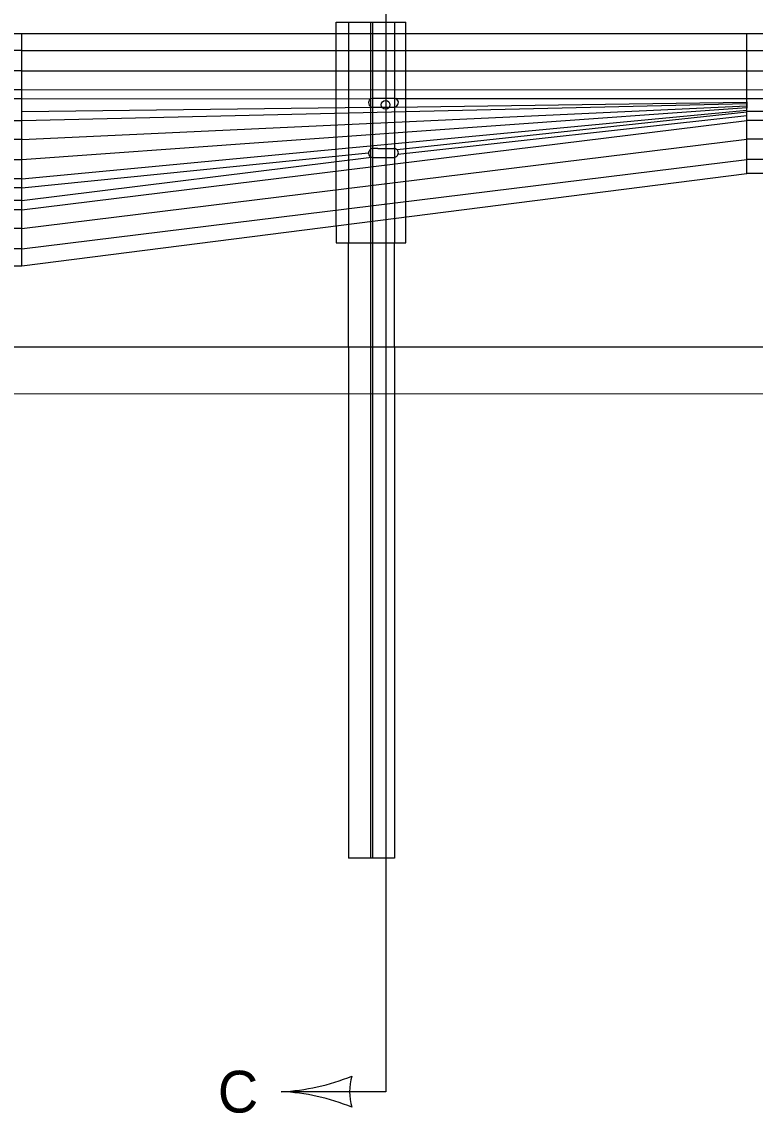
# Model space of a CAD drawing. Extents: x 49991 to 50160, y 49948 to 50051.
# Drawn here: x 50004.55 to 50005.602, y 49993.953 to 49995.519 of the extents above; entities that cross this region are included whole.
import ezdxf

# ---------------------------------------------------------------- set-up
doc = ezdxf.new("R2010")
doc.units = 0
for name, color, linetype in [('Level 1', 7, 'Continuous'), ('Level 2', 7, 'Continuous'), ('Level 3', 7, 'Continuous'), ('Level 4', 7, 'Continuous'), ('Level 6', 7, 'Continuous')]:
    doc.layers.add(name, color=color, linetype=linetype)

msp = doc.modelspace()

# ---------------------------------------------------------------- linework, layer by layer
at = {"layer": 'Level 1'}
for p, q in [((50005.0008, 49995.5185), (50005.1008, 49995.5185)), ((50005.0008, 49995.5019), (50005.0008, 49995.5185)), ((50005.0185, 49995.5185), (50005.0841, 49995.5185)), ((50005.1008, 49995.5019), (50005.1008, 49995.5185)), ((50004.3866, 49995.502), (50011.6716, 49995.5015)), ((50005.5897, 49995.3012), (50005.5897, 49995.5019)), ((50004.5497, 49995.4777), (50000.5693, 49995.4777)), ((50004.5497, 49995.4777), (50011.6716, 49995.4777)), ((50004.5497, 49995.4486), (50000.5693, 49995.4485)), ((50004.5497, 49995.4486), (50011.6716, 49995.448)), ((50004.5497, 49995.4215), (50000.5693, 49995.4215)), ((50004.5497, 49995.4215), (50011.6716, 49995.4225)), ((50005.0537, 49995.4094), (50005.0833, 49995.4094)), ((50004.5497, 49995.4085), (50003.4109, 49995.4084)), ((50004.5497, 49995.4085), (50005.0507, 49995.4087)), ((50005.5897, 49995.4012), (50004.5497, 49995.3769)), ((50004.5497, 49995.3499), (50005.5897, 49995.3982)), ((50004.5497, 49995.39), (50005.0523, 49995.3964)), ((50005.5897, 49995.3952), (50004.5497, 49995.3207)), ((50005.0537, 49995.3963), (50005.0833, 49995.3963)), ((50005.0833, 49995.3963), (50005.5897, 49995.4035)), ((50005.0854, 49995.409), (50011.6716, 49995.4068)), ((50005.5897, 49995.4041), (50005.5897, 49995.4023)), ((50005.5897, 49995.4023), (50005.5897, 49995.4004)), ((50005.5897, 49995.4004), (50005.5897, 49995.3986)), ((50005.5897, 49995.3986), (50005.5897, 49995.3968)), ((50005.5897, 49995.3968), (50005.5897, 49995.3949)), ((50004.5497, 49995.2937), (50005.5897, 49995.3923)), ((50005.0883, 49995.3354), (50005.5897, 49995.3898)), ((50005.0892, 49995.3288), (50005.5897, 49995.3846)), ((50011.6716, 49995.3902), (50005.5897, 49995.3903)), ((50004.5499, 49995.3769), (50000.5693, 49995.3769)), ((50004.5497, 49995.2491), (50005.5897, 49995.3773)), ((50011.6716, 49995.3773), (50005.5897, 49995.3773)), ((50004.5505, 49995.3499), (50000.5693, 49995.3499)), ((50004.5497, 49995.2221), (50005.5897, 49995.3504)), ((50011.6716, 49995.3504), (50005.5897, 49995.3504)), ((50005.0604, 49995.3373), (50005.0537, 49995.3373)), ((50005.0604, 49995.3373), (50005.0833, 49995.3373)), ((50004.5497, 49995.3207), (50000.5693, 49995.3207)), ((50004.5497, 49995.2806), (50005.0472, 49995.331)), ((50004.5497, 49995.2622), (50005.0514, 49995.3246)), ((50004.5497, 49995.1929), (50005.5897, 49995.3214)), ((50005.0514, 49995.3246), (50005.0537, 49995.3241)), ((50005.0537, 49995.3241), (50005.0833, 49995.3241)), ((50011.6716, 49995.3214), (50005.5897, 49995.3214)), ((50004.5497, 49995.1686), (50005.5897, 49995.3012)), ((50011.6716, 49995.3012), (50005.5897, 49995.3012)), ((50004.5497, 49995.2937), (50000.5693, 49995.2937)), ((50004.5497, 49995.2806), (50003.4116, 49995.2806)), ((50004.5497, 49995.2622), (50003.4083, 49995.2622)), ((50004.5497, 49995.2491), (50000.5693, 49995.2491)), ((50005.1008, 49995.2018), (50005.1008, 49995.2389)), ((50004.5497, 49995.2221), (50000.5693, 49995.2221)), ((50005.0008, 49995.2261), (50005.0008, 49995.2018)), ((50004.5497, 49995.1929), (50000.5693, 49995.1929)), ((50005.0008, 49995.2018), (50005.1008, 49995.2018)), ((50005.0185, 49995.0518), (50005.0185, 49995.2018)), ((50005.0841, 49995.0518), (50005.0841, 49995.2018)), ((50000.5693, 49995.1686), (50004.5497, 49995.1686)), ((50011.6716, 49995.0515), (50000.8175, 49995.052)), ((49999.8238, 49994.9854), (50011.6716, 49994.9849))]:
    msp.add_line(p, q, dxfattribs=at)
for points in [[(50005.0507, 49995.4087), (50005.0529, 49995.4094), (50005.0537, 49995.4094)], [(50005.0833, 49995.4094), (50005.0854, 49995.409), (50005.0863, 49995.4087)], [(50005.0508, 49995.397), (50005.0529, 49995.3963), (50005.0537, 49995.3963)], [(50005.0833, 49995.3963), (50005.0854, 49995.3967), (50005.087, 49995.3975)], [(50005.0537, 49995.3373), (50005.0516, 49995.3369), (50005.0501, 49995.3361)], [(50005.0833, 49995.3241), (50005.0854, 49995.3245), (50005.0873, 49995.3255), (50005.0887, 49995.3271), (50005.0893, 49995.3281), (50005.0897, 49995.3293)]]:
    msp.add_lwpolyline(points, dxfattribs=at)
msp.add_circle((50005.0716, 49995.3997), 0.00625, dxfattribs=at)
for centre, start, end in [((50005.0537, 49995.4029), 117.1386, 243.6106), ((50005.0833, 49995.4029), 304.6387, 62.8614), ((50005.0537, 49995.3307), 124.0204, 249.0228), ((50005.0833, 49995.3307), 347.308, 90)]:
    msp.add_arc(centre, 0.00656, start, end, dxfattribs=at)
at = {"layer": 'Level 3'}
for centre, radius, start, end in [((50004.9065, 49994.2937), 0.3107, 272.8273, 292.0772), ((50005.0928, 49993.9834), 0.073, 162.1388, 197.8612), ((50004.9096, 49993.6872), 0.2964, 67.456, 87.6395)]:
    msp.add_arc(centre, radius, start, end, dxfattribs=at)
at = {"layer": 'Level 4'}
for p, q in [((50005.0185, 49995.5185), (50005.0185, 49995.2018)), ((50005.0499, 49995.5185), (50005.0499, 49994.3185)), ((50005.0527, 49995.5185), (50005.0527, 49994.3185)), ((50005.0841, 49995.5185), (50005.0841, 49995.2018)), ((50004.5497, 49995.1686), (50004.5497, 49995.502)), ((50005.0008, 49995.2261), (50005.0008, 49995.5019)), ((50005.1008, 49995.2389), (50005.1008, 49995.5019)), ((50005.0185, 49995.0518), (50005.0185, 49994.3185)), ((50005.0841, 49995.0518), (50005.0841, 49994.3185)), ((50005.0841, 49994.3185), (50005.0185, 49994.3185))]:
    msp.add_line(p, q, dxfattribs=at)
at = {"layer": 'Level 6'}
for p, q in [((50005.0718, 49995.8222), (50005.0718, 49993.9834)), ((50005.0718, 49993.9834), (50004.9218, 49993.9834))]:
    msp.add_line(p, q, dxfattribs=at)

# ---------------------------------------------------------------- texts
at = {"layer": 'Level 2'}
msp.add_text('C', height=0.06, dxfattribs=at).set_placement((50004.8308, 49993.9534))

doc.saveas('drawing.dxf')
